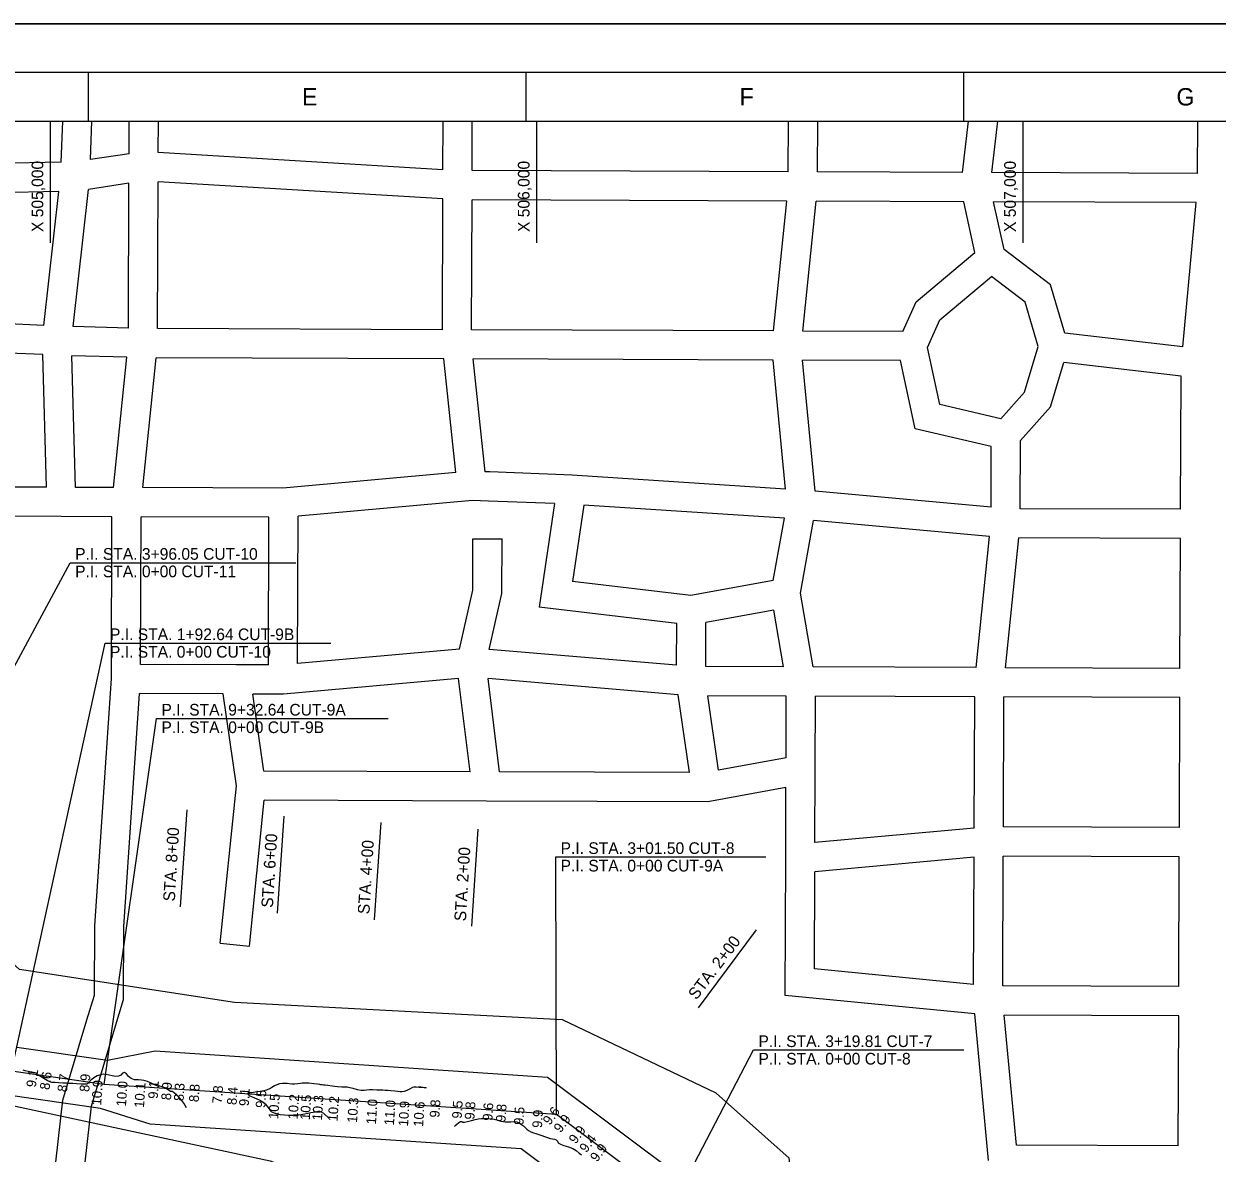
# Model space of a CAD drawing. Extents: x 501128 to 509328, y 1314906 to 1320706.
# Drawn here: x 504945 to 507399, y 1318384 to 1320706 of the extents above; entities that cross this region are included whole.
import ezdxf

# ---------------------------------------------------------------- set-up
doc = ezdxf.new("R2010")
doc.units = 0
for name, color, linetype in [('G-ANNO-TTLB', 7, 'Continuous'), ('Level 1', 7, 'Continuous'), ('Level 14', 7, 'Continuous'), ('Level 2', 7, 'Continuous'), ('Level 3', 7, 'Continuous'), ('Level 32', 7, 'Continuous'), ('Level 49', 7, 'Continuous'), ('Level 5', 7, 'Continuous'), ('Level 50', 7, 'Continuous'), ('Level 56', 7, 'Continuous'), ('Level 6', 7, 'Continuous')]:
    doc.layers.add(name, color=color, linetype=linetype)

msp = doc.modelspace()

# ---------------------------------------------------------------- linework, layer by layer
at = {"layer": 'G-ANNO-TTLB'}
for p, q in [((509228.1, 1320606.3), (501228.1, 1320606.3)), ((505078.1, 1320506.3), (505078.1, 1320606.3)), ((505978.1, 1320506.3), (505978.1, 1320606.3)), ((506878.1, 1320506.3), (506878.1, 1320606.3)), ((501478.1, 1320506.3), (509128.1, 1320506.3))]:
    msp.add_line(p, q, dxfattribs=at)
for points in [[(501128.1, 1314906.3), (509328.1, 1314906.3), (509328.1, 1320706.3), (501128.1, 1320706.3)], [(501128.1, 1314906.3), (509328.1, 1314906.3), (509328.1, 1320706.3), (501128.1, 1320706.3)], [(501128.1, 1320706.3), (509328.1, 1320706.3), (509328.1, 1314906.3), (501128.1, 1314906.3)]]:
    msp.add_lwpolyline(points, close=True, dxfattribs=at)
at = {"layer": 'Level 1'}
for points in [[(504985.8, 1318538), (504980.5, 1318541.1), (504977, 1318542.9), (504975.3, 1318543.6), (504974, 1318544.1), (504973.3, 1318544.4), (504973, 1318544.6), (504972.5, 1318545.3), (504971.8, 1318546.4), (504970.9, 1318548.1), (504967.5, 1318549.6), (504961.8, 1318551), (504953.6, 1318552.4), (504947.6, 1318553.6), (504943.6, 1318554.6)], [(505279.5, 1318477.3), (505274, 1318487), (505270.1, 1318492.3), (505265.2, 1318498), (505259.1, 1318504), (505254.2, 1318508.3), (505250.3, 1318510.7), (505247.6, 1318511.3), (505244.8, 1318512.5), (505241.8, 1318514.3), (505238.7, 1318516.7), (505235.2, 1318518.6), (505231.4, 1318520.1), (505227.3, 1318521.2), (505224.4, 1318521.8), (505222.6, 1318522), (505222, 1318521.6), (505218.9, 1318522.7), (505213.4, 1318525), (505205.3, 1318528.7), (505199, 1318531.4), (505194.5, 1318533.1), (505191.7, 1318533.8), (505187.1, 1318534.4), (505180.6, 1318534.9), (505172.4, 1318535.3), (505165.6, 1318537.5), (505160.1, 1318541.5), (505156.1, 1318547.3), (505152.1, 1318549.8), (505148.1, 1318548.9), (505144.2, 1318544.7), (505139.4, 1318542.4), (505133.7, 1318542), (505127, 1318543.5), (505120.7, 1318544.7), (505114.6, 1318545.7), (505108.8, 1318546.4), (505102.6, 1318545.5), (505096.1, 1318543), (505089.2, 1318538.9), (505084.6, 1318535.9), (505082.2, 1318534.3), (505082, 1318533.8), (505081.3, 1318532.8), (505080, 1318531.3), (505078.2, 1318529.3), (505076.6, 1318527.8), (505075.3, 1318526.8), (505074.3, 1318526.3), (505070.2, 1318526.1), (505063.2, 1318526.3), (505053.2, 1318526.8), (505045.6, 1318527.2), (505040.4, 1318527.4), (505037.5, 1318527.6), (505032.5, 1318527.9), (505025.5, 1318528.4), (505016.3, 1318529.1), (505009.4, 1318529.5), (505004.8, 1318529.7), (505002.5, 1318529.5), (504998.6, 1318530.9), (504993, 1318533.7), (504985.8, 1318538)], [(505756.6, 1318521.1), (505770.9, 1318519.1), (505772.4, 1318518.6), (505768.2, 1318518.7), (505758.2, 1318519.3), (505751.5, 1318519.7), (505747.8, 1318520), (505747.2, 1318520.1), (505744.5, 1318519), (505739.7, 1318516.8), (505732.9, 1318513.3), (505727.1, 1318511.1), (505722.5, 1318510.2), (505719, 1318510.6), (505714.1, 1318511), (505707.8, 1318511.6), (505700, 1318512.2), (505693.4, 1318512.8), (505687.9, 1318513.1), (505683.5, 1318513.4), (505677.9, 1318513.7), (505671, 1318514), (505662.8, 1318514.5), (505655.7, 1318514.4), (505649.6, 1318514), (505644.6, 1318513), (505638.4, 1318513.2), (505631, 1318514.6), (505622.4, 1318517), (505615.3, 1318518.7), (505609.6, 1318519.6), (505605.3, 1318519.7), (505598.8, 1318520.1), (505589.9, 1318520.9), (505578.8, 1318522.1), (505570.3, 1318523.1), (505564.5, 1318523.7), (505561.3, 1318524.1), (505558.5, 1318524.5), (505556, 1318525), (505553.9, 1318525.4), (505549.1, 1318526), (505541.6, 1318526.8), (505531.3, 1318527.9), (505523.9, 1318528.4), (505519.2, 1318528.4), (505517.4, 1318528), (505513.9, 1318527.5), (505508.7, 1318527), (505501.9, 1318526.4), (505495.9, 1318526.2), (505490.9, 1318526.5), (505486.7, 1318527.2), (505482, 1318527.5), (505476.8, 1318527.2), (505471.1, 1318526.5), (505465.6, 1318524.9), (505460.2, 1318522.5), (505455, 1318519.2), (505450.6, 1318516.7), (505447, 1318515), (505444.1, 1318513.9), (505438.8, 1318512.6), (505431.1, 1318511.1), (505421, 1318509.4)], [(505421, 1318509.4), (505413.8, 1318508.4), (505409.5, 1318508.3), (505408.1, 1318508.9), (505407, 1318508.9), (505406.3, 1318508.2), (505405.9, 1318506.9), (505405.9, 1318505.6), (505406.4, 1318504.5), (505407.4, 1318503.5), (505408.3, 1318502.7), (505409.1, 1318502.2), (505409.8, 1318501.9), (505413.4, 1318500.5), (505419.7, 1318497.8), (505428.9, 1318494), (505436.3, 1318489.7), (505442.1, 1318484.9), (505446.1, 1318479.6), (505449.4, 1318475.3), (505451.9, 1318472), (505453.5, 1318469.7), (505457.5, 1318467.6), (505463.8, 1318465.7), (505472.4, 1318463.9), (505481.3, 1318462.8), (505490.4, 1318462.4), (505499.8, 1318462.8), (505506.2, 1318462.9), (505509.7, 1318462.9), (505510.2, 1318462.7), (505514.7, 1318463.4), (505523, 1318465), (505535.3, 1318467.6), (505544.5, 1318469.4), (505550.4, 1318470.4), (505553.1, 1318470.8), (505556.8, 1318469.3), (505561.4, 1318466.2), (505572.5, 1318456.3)], [(505832.1, 1318439.1), (505831.1, 1318439.4), (505832.2, 1318440.8), (505835.1, 1318443.3), (505839.6, 1318447.1), (505843.2, 1318449.1), (505845.8, 1318449.5), (505847.4, 1318448.2), (505851.2, 1318448.1), (505857.2, 1318449.3), (505865.4, 1318451.7), (505872.9, 1318453.5), (505879.8, 1318454.8), (505885.9, 1318455.4), (505892.4, 1318455.6), (505899.2, 1318455.4), (505906.4, 1318454.8), (505912.5, 1318453.8), (505917.6, 1318452.6), (505921.6, 1318451.1), (505925.9, 1318450), (505930.4, 1318449.1), (505935.1, 1318448.5), (505940.5, 1318448.3), (505946.4, 1318448.6), (505953, 1318449.2), (505958.8, 1318448.5), (505963.9, 1318446.6), (505968.4, 1318443.4), (505972.4, 1318440.2), (505975.9, 1318436.8), (505979.1, 1318433.5), (505982.9, 1318430.6), (505987.6, 1318428.2), (505993, 1318426.3), (505997.8, 1318424.6), (506002.1, 1318423.1), (506005.8, 1318421.8), (506010.4, 1318420.3), (506015.7, 1318418.4), (506021.9, 1318416.3), (506027.4, 1318414.6), (506032.1, 1318413.5), (506036.2, 1318412.9), (506039.6, 1318411.4), (506042.2, 1318408.9), (506044.1, 1318405.5), (506048.6, 1318402.4), (506055.6, 1318399.8), (506065.2, 1318397.4), (506073.7, 1318394.1), (506081, 1318389.7), (506087.1, 1318384.3), (506091.7, 1318380.8)]]:
    msp.add_lwpolyline(points, dxfattribs=at)
at = {"layer": 'Level 14'}
for p, q in [((507358.7, 1320398.8), (507359.1, 1320506.3)), ((507328.1, 1320042), (507355.5, 1320338.8)), ((507323.8, 1319708.2), (507324.8, 1319982)), ((507322.5, 1319381), (507323.6, 1319648.2)), ((507321.3, 1319053.8), (507322.3, 1319321)), ((507320.1, 1318726.6), (507321.1, 1318993.8)), ((507318.8, 1318399.4), (507319.9, 1318666.6))]:
    msp.add_line(p, q, dxfattribs=at)
at = {"layer": 'Level 2'}
for p, q in [((505000, 1320256.3), (505000, 1320506.3)), ((506000, 1320256.3), (506000, 1320506.3)), ((507000, 1320256.3), (507000, 1320506.3))]:
    msp.add_line(p, q, dxfattribs=at)
at = {"layer": 'Level 32'}
for p, q in [((505021.6, 1320421.6), (505025, 1320506.3)), ((505081.9, 1320427.2), (505085, 1320506.3)), ((505161.4, 1320439.2), (505161.7, 1320506.3)), ((505221.4, 1320441.6), (505221.7, 1320506.3)), ((505806.9, 1320406.4), (505807.3, 1320506.3)), ((505866.9, 1320404.5), (505867.3, 1320506.3)), ((506517.1, 1320402), (506517.5, 1320506.3)), ((506577.1, 1320401.8), (506577.5, 1320506.3)), ((506875.3, 1320400.7), (506887.5, 1320506.3)), ((506935.7, 1320400.4), (506947.9, 1320506.3)), ((505161.4, 1320439.2), (505081.9, 1320427.2)), ((505806.9, 1320406.4), (505221.4, 1320441.6)), ((505021.6, 1320421.6), (504829.3, 1320417.8)), ((506517.1, 1320402), (505866.9, 1320404.5)), ((506875.3, 1320400.7), (506577.1, 1320401.8)), ((507358.7, 1320398.8), (506935.7, 1320400.4)), ((505016.9, 1320361.5), (504828.4, 1320357.8)), ((504986.3, 1320086.1), (505016.9, 1320361.5)), ((505046.5, 1320084), (505077.8, 1320365.9)), ((505161.2, 1320378.5), (505077.8, 1320365.9)), ((505160.1, 1320080.7), (505161.2, 1320378.5)), ((505220.1, 1320079.7), (505221.2, 1320381.6)), ((505806.7, 1320346.3), (505221.2, 1320381.6)), ((505805.7, 1320077.5), (505806.7, 1320346.3)), ((505865.7, 1320077.3), (505866.7, 1320344.5)), ((506513.8, 1320342), (505866.7, 1320344.5)), ((506486.4, 1320074.9), (506513.8, 1320342)), ((506546.7, 1320074.7), (506574.1, 1320341.8)), ((506877.9, 1320340.6), (506574.1, 1320341.8)), ((506900.6, 1320236.3), (506877.9, 1320340.6)), ((507355.5, 1320338.8), (506939.3, 1320340.4)), ((506960.7, 1320242.2), (506939.3, 1320340.4)), ((504986.3, 1320086.1), (504913.9, 1320089.3)), ((505160.1, 1320080.7), (505046.5, 1320084)), ((505805.7, 1320077.5), (505220.1, 1320079.7)), ((506486.4, 1320074.9), (505865.7, 1320077.3)), ((506752.3, 1320073.9), (506546.7, 1320074.7)), ((507328.1, 1320042), (507085.5, 1320070.2)), ((504983.8, 1320026.1), (504896.1, 1320030)), ((504991.3, 1319753.4), (504983.8, 1320026.1)), ((505051.3, 1319753.2), (505043.9, 1320024)), ((505156.8, 1320020.8), (505043.9, 1320024)), ((505129.3, 1319752.9), (505156.8, 1320020.8)), ((505189.6, 1319752.7), (505217, 1320019.7)), ((505808.6, 1320017.5), (505217, 1320019.7)), ((505833.7, 1319783.6), (505808.6, 1320017.5)), ((505893.8, 1319785.5), (505869, 1320017.3)), ((506486.2, 1320014.9), (505869, 1320017.3)), ((506511.3, 1319749.7), (506486.2, 1320014.9)), ((506572, 1319745.1), (506546.5, 1320014.7)), ((506747.5, 1320013.9), (506546.5, 1320014.7)), ((507324.8, 1319982), (507083.7, 1320010)), ((506994.1, 1319709.4), (506994.7, 1319849.8)), ((506934.1, 1319712.4), (506934.6, 1319837.5)), ((505833.7, 1319783.6), (505477.9, 1319751.6)), ((505903, 1319785.2), (505893.8, 1319785.5)), ((506072.3, 1319778.3), (505903.1, 1319785.2)), ((506511.3, 1319749.7), (506072.3, 1319778.3)), ((504991.3, 1319753.4), (504855.6, 1319753.9)), ((505129.3, 1319752.9), (505051.3, 1319753.2)), ((505477.9, 1319751.6), (505189.6, 1319752.7)), ((505867.6, 1319726.4), (505509.1, 1319694.1)), ((505900.7, 1319725.2), (505867.6, 1319726.4)), ((506036.2, 1319719.8), (505900.7, 1319725.2)), ((506934.1, 1319712.4), (506572, 1319745.1)), ((506036.2, 1319719.8), (506004.7, 1319507.1)), ((506096.4, 1319716.6), (506073.1, 1319559.4)), ((506509, 1319689.8), (506096.4, 1319716.6)), ((507323.8, 1319708.2), (506994.1, 1319709.4)), ((505022, 1319693.3), (504820.6, 1319694.1)), ((505126.3, 1319692.9), (505022, 1319693.3)), ((505125, 1319360.3), (505126.3, 1319692.9)), ((505185.1, 1319389.1), (505186.3, 1319692.7)), ((505449.1, 1319691.7), (505186.3, 1319692.7)), ((505448, 1319388.1), (505449.1, 1319691.7)), ((505508, 1319390.8), (505509.1, 1319694.1)), ((506485.7, 1319561.6), (506509, 1319689.8)), ((506542, 1319535.7), (506569.1, 1319685.2)), ((506931.1, 1319652.4), (506569.1, 1319685.2)), ((506903.4, 1319382.6), (506931.1, 1319652.4)), ((506963.7, 1319382.4), (506991.1, 1319649.5)), ((507323.6, 1319648.2), (506991.1, 1319649.5)), ((505868.6, 1319647.4), (505928.6, 1319647.1)), ((506316.7, 1319530.6), (506073.1, 1319559.4)), ((506485.7, 1319561.6), (506316.7, 1319530.6)), ((506568.4, 1319383.9), (506542, 1319535.7)), ((506287.6, 1319473.6), (506004.7, 1319507.1)), ((506487.2, 1319500.9), (506347.6, 1319475.2)), ((506507.4, 1319384.1), (506487.2, 1319500.9)), ((506287.3, 1319387.4), (506287.6, 1319473.6)), ((506347.3, 1319384.7), (506347.6, 1319475.2)), ((505840.9, 1319420.8), (505508, 1319390.8)), ((506287.3, 1319387.4), (505902.2, 1319419.9)), ((505381.1, 1319388.4), (505185.1, 1319389.1)), ((505448, 1319388.1), (505381.1, 1319388.4)), ((506507.4, 1319384.1), (506347.3, 1319384.7)), ((506903.4, 1319382.6), (506568.4, 1319383.9)), ((507322.5, 1319381), (506963.7, 1319382.4)), ((505090.8, 1318851.4), (505125, 1319360.3)), ((505839.1, 1319360.4), (505479.1, 1319328)), ((505862.7, 1319168.4), (505839.1, 1319360.4)), ((505923.2, 1319168.2), (505899.6, 1319359.9)), ((506290.9, 1319326.9), (505899.6, 1319359.9)), ((505150.8, 1318849.3), (505183.1, 1319329.1)), ((505355, 1319328.5), (505183.1, 1319329.1)), ((505382.2, 1319139.5), (505355, 1319328.5)), ((505438.4, 1319170), (505415.6, 1319328.2)), ((505479.1, 1319328), (505415.6, 1319328.2)), ((506314, 1319166.7), (506290.9, 1319326.9)), ((506373.8, 1319171.7), (506351.8, 1319324.7)), ((506513, 1319324.1), (506351.8, 1319324.7)), ((506512.5, 1319197.2), (506513, 1319324.1)), ((506572.4, 1319172.1), (506573, 1319323.8)), ((506900.4, 1319322.6), (506573, 1319323.8)), ((506899.4, 1319052.7), (506900.4, 1319322.6)), ((506959.4, 1319055.2), (506960.4, 1319322.4)), ((507322.3, 1319321), (506960.4, 1319322.4)), ((506512.5, 1319197.2), (506373.8, 1319171.7)), ((505862.7, 1319168.4), (505438.4, 1319170)), ((506314, 1319166.7), (505923.2, 1319168.2)), ((506571.9, 1319023.2), (506572.4, 1319172.1)), ((505349.1, 1318816.1), (505382.2, 1319139.5)), ((506512.3, 1319136.1), (506351.3, 1319106.5)), ((506511.7, 1318990.5), (506512.3, 1319136.1)), ((505408.8, 1318810), (505439.5, 1319110)), ((505896.5, 1319108.3), (505439.5, 1319110)), ((506351.3, 1319106.5), (505896.5, 1319108.3)), ((506899.4, 1319052.7), (506571.9, 1319023.2)), ((507321.3, 1319053.8), (506959.4, 1319055.2)), ((506510.7, 1318708.7), (506511.7, 1318990.5)), ((506899.1, 1318992.5), (506571.6, 1318963)), ((506898.1, 1318731.2), (506899.1, 1318992.5)), ((506958.1, 1318728), (506959.1, 1318995.2)), ((507321.1, 1318993.8), (506959.1, 1318995.2)), ((506570.9, 1318763.1), (506571.6, 1318963)), ((505090.3, 1318709.4), (505090.8, 1318851.4)), ((505150.2, 1318700.5), (505150.8, 1318849.3)), ((505349.1, 1318816.1), (505408.8, 1318810)), ((506898.1, 1318731.2), (506570.9, 1318763.1)), ((507320.1, 1318726.6), (506958.1, 1318728)), ((505074.8, 1318658.4), (505090.3, 1318709.4)), ((505132.3, 1318641.1), (505150.2, 1318700.5)), ((506900.5, 1318670.6), (506510.7, 1318708.7)), ((506929.1, 1318369.4), (506900.5, 1318670.6)), ((506986.4, 1318400.7), (506961, 1318668)), ((507319.9, 1318666.6), (506961, 1318668)), ((505025.3, 1318493.1), (505074.8, 1318658.4)), ((505084.3, 1318481), (505132.3, 1318641.2)), ((504996, 1318238.1), (505025.3, 1318493.1)), ((505054.5, 1318221.3), (505084.3, 1318481)), ((507318.8, 1318399.4), (506986.4, 1318400.7))]:
    msp.add_line(p, q, dxfattribs=at)
for points in [[(507085.5, 1320070.2), (507056.4, 1320169.9), (506960.7, 1320242.2)], [(506752.3, 1320073.9), (506779.7, 1320135), (506900.6, 1320236.3)], [(506803.1, 1320040.6), (506828.8, 1320097.9), (506934.8, 1320186.7)], [(507030.9, 1320042.9), (507004.3, 1320134), (506934.8, 1320186.7)], [(506954.1, 1319894.5), (507002.7, 1319948.8), (507030.9, 1320042.9)], [(506954.1, 1319894.5), (506828.7, 1319923.3), (506803.1, 1320040.6)], [(506934.6, 1319837.5), (506778.2, 1319873.3), (506747.5, 1320013.9)], [(506994.7, 1319849.8), (507056.4, 1319918.8), (507083.7, 1320010)], [(505840.9, 1319420.8), (505868.2, 1319541.6), (505868.6, 1319647.4)], [(505902.2, 1319419.9), (505928.2, 1319534.8), (505928.6, 1319647.1)]]:
    msp.add_lwpolyline(points, dxfattribs=at)
at = {"layer": 'Level 5'}
for points in [[(502988.5, 1320506.3), (503056.9, 1320142.4), (503189.4, 1319858.7), (503438.4, 1319516.2), (504086.3, 1318789.2), (504252.7, 1318680.4), (504544, 1318562.8), (505451.9, 1318368.4), (505926.4, 1318183.7), (506109.2, 1317999.8), (506132.4, 1317399.6), (506064.1, 1316858.1), (505929.2, 1316350.1), (505744.2, 1315800.6), (505760.3, 1315617.2), (505843.1, 1315416.9), (505867.7, 1315106.3)], [(506133.9, 1315106.3), (506134.1, 1315191), (506100.8, 1315216.1), (506088.6, 1315786), (506137, 1316149.5), (506179.5, 1316449.4), (506272.3, 1316790.8), (506340.8, 1317415.6), (506508.7, 1317823.5), (506567.6, 1317998.4), (506518.7, 1318373.6), (506369, 1318507.4), (506052.8, 1318658.3), (505377.9, 1318693.7), (504936.3, 1318761.6), (504770.1, 1318912.2), (504728.7, 1319020.6), (504387.5, 1319163.3), (503822.6, 1319798.4), (503531.7, 1320041), (503232.9, 1320458.6), (503215.7, 1320506.3)]]:
    msp.add_lwpolyline(points, dxfattribs=at)
at = {"layer": 'Level 50'}
for p, q in [((505117.2, 1318575), (504930.9, 1318601.8)), ((505214.8, 1318593.7), (505117.2, 1318575)), ((506022, 1318540), (505214.8, 1318593.7)), ((506324, 1318314.1), (506022, 1318540)), ((505102.9, 1318476.1), (504907.8, 1318504.1)), ((505204.8, 1318444.1), (505102.9, 1318476.1)), ((505967.7, 1318393.3), (505204.8, 1318444.1)), ((506198.1, 1318220.9), (505967.7, 1318393.3))]:
    msp.add_line(p, q, dxfattribs=at)
at = {"layer": 'Level 56'}
for p, q in [((504543.5, 1318677.6), (505040.5, 1319598.4)), ((505040.5, 1319598.4), (505504.5, 1319598.4)), ((504919.4, 1318552.9), (505112.2, 1319433.1)), ((505112.2, 1319433.1), (505576.2, 1319433.1)), ((505110.1, 1318525.5), (505218.1, 1319278)), ((505218.1, 1319278), (505694.4, 1319278)), ((505267.3, 1318890.9), (505280.6, 1319090.5)), ((505466.9, 1318877.6), (505480.2, 1319077.2)), ((505666.4, 1318864.3), (505679.7, 1319063.9)), ((505866, 1318851), (505879.3, 1319050.6)), ((506040.6, 1318463.6), (506038.8, 1318993.4)), ((506038.8, 1318993.4), (506471, 1318993.4)), ((506451.3, 1318843.2), (506331.5, 1318683.1)), ((506282.1, 1318283), (506445.8, 1318596.4)), ((506445.8, 1318596.4), (506878, 1318596.4))]:
    msp.add_line(p, q, dxfattribs=at)
at = {"layer": 'Level 6'}
for p, q in [((505110.1, 1318525.5), (504919.4, 1318552.9)), ((506040.6, 1318463.6), (505110.1, 1318525.5)), ((506282.1, 1318283), (506040.6, 1318463.6))]:
    msp.add_line(p, q, dxfattribs=at)

# ---------------------------------------------------------------- texts
at = {"layer": 'G-ANNO-TTLB'}
for s, p in [('E', (505516.9, 1320538.5)), ('F', (506416.9, 1320538.5)), ('G', (507315.3, 1320538.5))]:
    msp.add_text(s, height=35.7, dxfattribs=at).set_placement(p)
at = {"layer": 'Level 3'}
for s, p in [('X 505,000', (504985, 1320278.3)), ('X 506,000', (505985, 1320278.3)), ('X 507,000', (506985, 1320278.3))]:
    msp.add_text(s, height=24, rotation=90, dxfattribs=at).set_placement(p)
at = {"layer": 'Level 49'}
for s, rotation, p in [('9.1', 81.8319, (504969.5, 1318518.6)), ('8.6', 81.8319, (504997.4, 1318513.4)), ('8.7', 81.8319, (505033.4, 1318508.9)), ('8.9', 86.1908, (505079.4, 1318509.6)), ('10.9 ', 86.1908, (505104, 1318481.9)), ('10.0 ', 86.1908, (505155, 1318479.9)), ('10.1 ', 86.1908, (505192, 1318476.9)), ('9.1', 86.1908, (505220.4, 1318495.4)), ('8.9', 86.1908, (505247.4, 1318492.6)), ('8.3', 86.1908, (505273.4, 1318490.7)), ('8.8', 86.1908, (505304.4, 1318488.7)), ('7.8', 86.1908, (505352.4, 1318485.7)), ('8.4', 86.1908, (505382.4, 1318482.7)), ('9.1', 86.1908, (505407.4, 1318480.4)), ('9.5', 86.1908, (505441.4, 1318476.7)), ('10.5 ', 86.1908, (505468, 1318453.9)), ('10.2 ', 86.1908, (505508, 1318452.9)), ('10.5 ', 86.1908, (505533, 1318451.9)), ('10.3 ', 86.1908, (505558, 1318450.9)), ('10.2 ', 86.1908, (505590, 1318448.9)), ('10.3 ', 86.1908, (505630, 1318445.9)), ('11.0 ', 86.1908, (505669, 1318442.9)), ('11.0 ', 86.1908, (505706, 1318440.9)), ('10.9 ', 86.1908, (505735, 1318438.9)), ('10.6 ', 86.1908, (505766, 1318437.9)), ('9.8', 86.1908, (505799.4, 1318456.7)), ('9.5', 86.1908, (505845.4, 1318454.7)), ('9.8', 86.1908, (505871.4, 1318452.7)), ('9.6', 86.1908, (505908.3, 1318450.2)), ('9.8', 86.1908, (505935.4, 1318447.7)), ('9.5', 86.1908, (505972.4, 1318441.7)), ('9.9', 86.1908, (506010.4, 1318435.6)), ('9.6', 53.2061, (506026.5, 1318440.3)), ('9.9', 53.2061, (506048.8, 1318424.7)), ('9.9', 53.2061, (506079.8, 1318401.7)), ('9.4', 53.2061, (506101.8, 1318383.7)), ('9.9', 53.2061, (506123.8, 1318364.7))]:
    msp.add_text(s, height=20, rotation=rotation, dxfattribs=at).set_placement(p)
at = {"layer": 'Level 56'}
for s, p in [('P.I. STA. 3+96.05 CUT-10', (505050.5, 1319604.4)), ('P.I. STA. 0+00 CUT-11', (505050.5, 1319568.4)), ('P.I. STA. 1+92.64 CUT-9B', (505122.2, 1319439.1)), ('P.I. STA. 0+00 CUT-10', (505122.2, 1319403.1)), ('P.I. STA. 9+32.64 CUT-9A', (505228, 1319284)), ('P.I. STA. 0+00 CUT-9B', (505228, 1319248)), ('P.I. STA. 3+01.50 CUT-8', (506048.8, 1318999.4)), ('P.I. STA. 0+00 CUT-9A', (506048.8, 1318963.4)), ('P.I. STA. 3+19.81 CUT-7', (506455.7, 1318602.4)), ('P.I. STA. 0+00 CUT-8', (506455.7, 1318566.4))]:
    msp.add_text(s, height=24, dxfattribs=at).set_placement(p)
for s, rotation, p in [('STA. 8+00', 86.5204, (505255.4, 1318901.2)), ('STA. 6+00', 86.5204, (505457.2, 1318888.3)), ('STA. 4+00', 86.5204, (505655.6, 1318875)), ('STA. 2+00', 86.5204, (505854.1, 1318860.6)), ('STA. 2+00', 52.8313, (506328.3, 1318698))]:
    msp.add_text(s, height=24, rotation=rotation, dxfattribs=at).set_placement(p)

doc.saveas('drawing.dxf')
